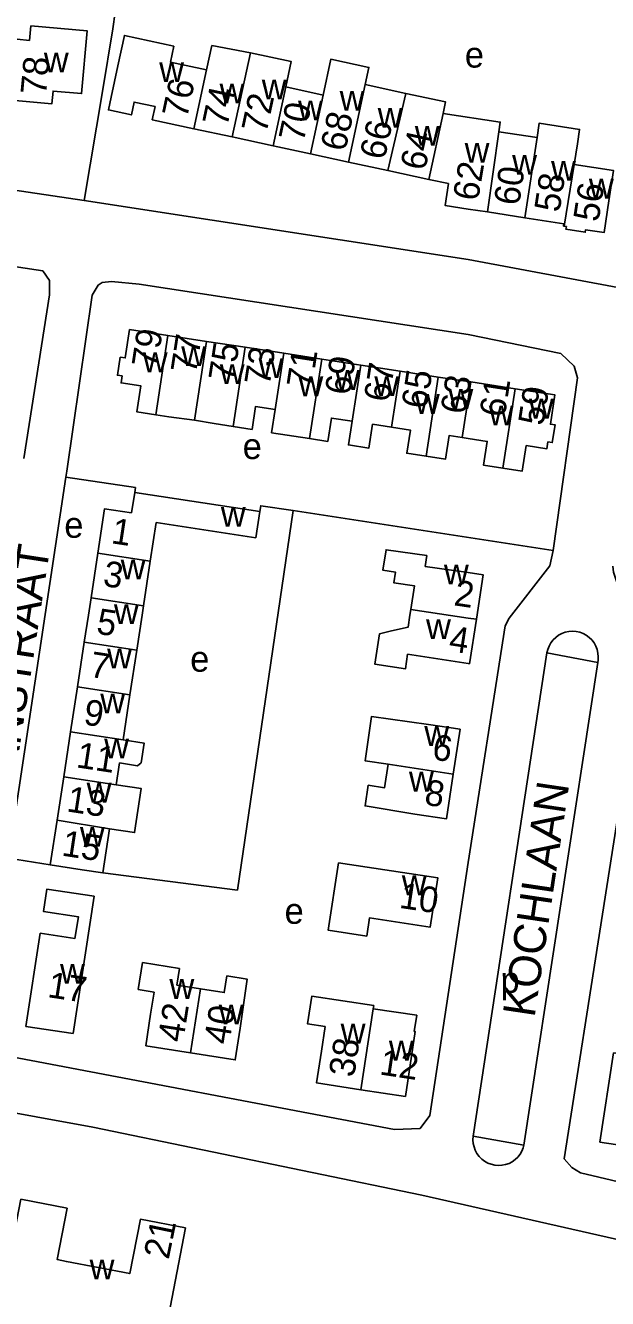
# Model space of a CAD drawing. Extents: x 161093 to 163177, y 379000 to 380904.
# Drawn here: x 161831.1 to 161921.7, y 380393.8 to 380591.7 of the extents above; entities that cross this region are included whole.
import ezdxf

# ---------------------------------------------------------------- set-up
doc = ezdxf.new("R2010")
doc.units = 0
for name, color, linetype in [('BLT_Basislijn', 7, 'Continuous'), ('BLT_Bebouwing', 7, 'Continuous'), ('BLT_Centroide', 7, 'Continuous'), ('BLT_Huisnummer', 7, 'Continuous'), ('BLT_Huisnummer_ tussenligend', 7, 'Continuous'), ('BLT_Onderverdeling_panden', 7, 'Continuous'), ('BLT_Straatnaam', 7, 'Continuous')]:
    doc.layers.add(name, color=color, linetype=linetype)

msp = doc.modelspace()

# ---------------------------------------------------------------- linework, layer by layer
at = {"layer": 'BLT_Basislijn'}
for p, q in [((161765.74, 380575.56), (161840.27, 380564.46)), ((161837.58, 380522.41), (161837.43, 380521.48)), ((161837.43, 380521.48), (161828.52, 380462.26)), ((161872.79, 380516.26), (161864.12, 380457.28)), ((161913.21, 380510.04), (161872.79, 380516.26)), ((161912.24, 380494.13), (161900.78, 380419.03)), ((161912.24, 380494.13), (161920.14, 380492.66)), ((161920.14, 380492.66), (161908.67, 380417.63)), ((161834.99, 380461.19), (161828.52, 380462.26)), ((161843.17, 380459.95), (161864.12, 380457.28)), ((161900.78, 380419.03), (161908.67, 380417.63))]:
    msp.add_line(p, q, dxfattribs=at)
for points in [[(161846.89, 380606.73), (161844.74, 380591.17), (161843.14, 380581.41), (161840.27, 380564.46)], [(161754.75, 380535.6), (161755.89, 380544.7), (161758.65, 380561.45), (161760.72, 380563.99), (161763.58, 380564.09), (161833.83, 380553.53), (161834.89, 380552.05), (161834.86, 380549.82), (161830.91, 380524.37)], [(161924.08, 380550.81), (161900, 380555.29), (161840.27, 380564.46)], [(161913.21, 380510.04), (161917, 380536.92), (161916.46, 380538.73), (161914.39, 380540.68), (161900, 380543.62), (161848.8, 380551.49), (161844.5, 380551.89), (161843.07, 380551.7), (161842.45, 380551.33), (161841.52, 380549.75), (161837.58, 380522.41)], [(161848.13, 380519.09), (161848.24, 380519.84), (161837.43, 380521.48)], [(161872.79, 380516.26), (161867.74, 380517.03), (161867.6, 380516.11)], [(161828.52, 380462.26), (161824.59, 380437.84), (161824.62, 380435.09), (161825.13, 380433.29), (161825.61, 380432.73), (161827.94, 380431.56), (161888.53, 380420.08), (161892.51, 380420.22), (161894.01, 380422.22), (161900, 380461.58), (161905.75, 380498.33), (161906.39, 380499.55), (161912.7, 380507.69), (161913.21, 380510.04)], [(161922.51, 380507.63), (161922.58, 380506.72), (161926.97, 380493.62), (161926.83, 380491.57), (161914.93, 380415.47), (161916.11, 380414.16), (161917.48, 380413.33), (161971.38, 380400.58), (161982.94, 380398.28), (161983.54, 380401.47)], [(161912.24, 380494.13), (161912.37, 380494.69), (161912.57, 380495.21), (161912.85, 380495.71), (161913.2, 380496.16), (161913.6, 380496.55), (161914.06, 380496.89), (161914.56, 380497.16), (161915.09, 380497.35), (161915.65, 380497.47), (161916.21, 380497.51), (161916.78, 380497.47), (161917.33, 380497.35), (161917.86, 380497.15), (161918.36, 380496.88), (161918.82, 380496.54), (161919.22, 380496.15), (161919.56, 380495.69), (161919.84, 380495.2), (161920.05, 380494.67), (161920.17, 380494.12), (161920.22, 380493.55), (161920.19, 380492.99), (161920.14, 380492.66)], [(161790.41, 380429.73), (161841.6, 380420.4), (161892.77, 380409.85), (161973.76, 380391.48), (162004.17, 380383.95)], [(161900.78, 380419.03), (161900.74, 380418.47), (161900.78, 380417.9), (161900.9, 380417.35), (161901.09, 380416.82), (161901.36, 380416.32), (161901.7, 380415.86), (161902.09, 380415.46), (161902.54, 380415.12), (161903.04, 380414.84), (161903.57, 380414.64), (161904.12, 380414.51), (161904.68, 380414.46), (161905.25, 380414.49), (161905.8, 380414.6), (161906.34, 380414.79), (161906.84, 380415.05), (161907.3, 380415.38), (161907.71, 380415.77), (161908.06, 380416.21), (161908.35, 380416.7), (161908.56, 380417.22), (161908.67, 380417.63)]]:
    msp.add_lwpolyline(points, dxfattribs=at)
at = {"layer": 'BLT_Bebouwing'}
for p, q in [((161871.61, 380582.12), (161877.42, 380580.87)), ((161863.31, 380574.35), (161857.35, 380575.63)), ((161869.64, 380572.98), (161863.31, 380574.35)), ((161875.45, 380571.73), (161869.64, 380572.98)), ((161881.38, 380570.45), (161875.45, 380571.73)), ((161887.51, 380569.13), (161881.38, 380570.45)), ((161893.88, 380567.76), (161887.51, 380569.13)), ((161908.8, 380561.8), (161902.97, 380562.69)), ((161859.31, 380542.57), (161853.3, 380543.5)), ((161865.33, 380541.65), (161859.31, 380542.57)), ((161871.31, 380540.73), (161865.33, 380541.65)), ((161877.21, 380539.82), (161871.31, 380540.73)), ((161883.28, 380538.89), (161877.21, 380539.82)), ((161889.4, 380537.95), (161883.28, 380538.89)), ((161895.34, 380537.03), (161889.4, 380537.95)), ((161907.29, 380535.2), (161900.4, 380536.26)), ((161847.65, 380515.92), (161848.13, 380519.09)), ((161848.13, 380519.09), (161867.6, 380516.11)), ((161866.98, 380512.04), (161867.6, 380516.11)), ((161851.48, 380514.41), (161850.56, 380508.4)), ((161851.48, 380514.41), (161866.98, 380512.04)), ((161841.34, 380502.72), (161842.4, 380509.64)), ((161849.5, 380501.48), (161850.56, 380508.4)), ((161840.92, 380500), (161841.34, 380502.72)), ((161840.28, 380495.8), (161840.92, 380500)), ((161849.28, 380500), (161848.45, 380494.55)), ((161849.28, 380500), (161849.5, 380501.48)), ((161900.22, 380492.47), (161901.27, 380499.37)), ((161839.22, 380488.88), (161840.28, 380495.8)), ((161848.45, 380494.55), (161847.39, 380487.63)), ((161838.15, 380481.87), (161839.22, 380488.88)), ((161847.39, 380487.63), (161846.33, 380480.62)), ((161837.09, 380474.9), (161838.15, 380481.87)), ((161836.05, 380468.12), (161837.09, 380474.9)), ((161834.99, 380461.19), (161836.05, 380468.12)), ((161844.22, 380466.82), (161843.17, 380459.95)), ((161841.81, 380456.31), (161838.57, 380434.97)), ((161831.21, 380436.09), (161833.41, 380450.59)), ((161848.68, 380441.81), (161849.34, 380445.99)), ((161849.34, 380445.99), (161855.09, 380445.08)), ((161855.09, 380445.08), (161854.69, 380442.51)), ((161854.69, 380442.51), (161858.38, 380441.93)), ((161851.15, 380441.42), (161848.68, 380441.81)), ((161850.61, 380437.99), (161851.15, 380441.42)), ((161849.84, 380433.05), (161850.61, 380437.99)), ((161838.57, 380434.97), (161831.21, 380436.09)), ((161856.81, 380431.96), (161849.84, 380433.05))]:
    msp.add_line(p, q, dxfattribs=at)
for points in [[(161828.98, 380580.09), (161835.25, 380579.51), (161835.43, 380581.49), (161839.87, 380581.08), (161840.72, 380590.85), (161831.99, 380591.62), (161831.77, 380589.35), (161829.85, 380589.53)], [(161851.31, 380579.07), (161848.04, 380579.78), (161847.61, 380577.78), (161844.04, 380578.55), (161844.46, 380580.55), (161845.52, 380585.43), (161846.53, 380590.13), (161854.21, 380588.47)], [(161854.21, 380588.47), (161853.68, 380585.98), (161859.32, 380584.76)], [(161859.32, 380584.76), (161860.14, 380588.56), (161866.16, 380587.43)], [(161866.16, 380587.43), (161872.46, 380586.08), (161871.61, 380582.12)], [(161877.42, 380580.87), (161878.62, 380586.44), (161884.55, 380585.16), (161883.97, 380582.48)], [(161883.97, 380582.48), (161890.3, 380581.12)], [(161890.3, 380581.12), (161896.47, 380579.79), (161896.09, 380578.01)], [(161857.35, 380575.63), (161850.87, 380577.02), (161851.31, 380579.07)], [(161896.09, 380578.01), (161904.99, 380576.65), (161904.75, 380575.15)], [(161904.75, 380575.15), (161910.7, 380574.24)], [(161910.7, 380574.24), (161911.02, 380576.49), (161917.31, 380575.53), (161916.97, 380573.28), (161916.48, 380570.05)], [(161916.48, 380570.05), (161922.6, 380569.11), (161921.89, 380564.44), (161921.13, 380559.49), (161918.26, 380559.93), (161918.2, 380559.54), (161915.2, 380560), (161915.27, 380560.42), (161914.94, 380560.47)], [(161902.97, 380562.69), (161900, 380563.15), (161896.39, 380563.7), (161896.91, 380567.11), (161893.88, 380567.76)], [(161914.94, 380560.47), (161914.82, 380560.49), (161914.88, 380560.87), (161908.8, 380561.8)], [(161853.3, 380543.5), (161847.34, 380544.41), (161846.66, 380540), (161845.88, 380540.11), (161845.45, 380537.3), (161846.17, 380537.19), (161846, 380536.11), (161849.1, 380535.64), (161848.48, 380531.6), (161851.41, 380531.15)], [(161900.4, 380536.26), (161900, 380536.32), (161895.34, 380537.03)], [(161905.39, 380522.86), (161908.4, 380522.4), (161909.01, 380526.36), (161912.23, 380525.87), (161912.4, 380526.94), (161913.07, 380526.84), (161913.5, 380529.6), (161912.79, 380529.7), (161913.49, 380534.24), (161907.29, 380535.2)], [(161869.97, 380532), (161866.93, 380532.47), (161866.38, 380528.89), (161863.44, 380529.35)], [(161875.31, 380527.46), (161869.41, 380528.36), (161869.97, 380532)], [(161851.41, 380531.15), (161853.42, 380530.84), (161857.42, 380530.31)], [(161863.44, 380529.35), (161860.5, 380529.8), (161857.42, 380530.31)], [(161881.94, 380530.17), (161878.72, 380530.66), (161878.16, 380527.02), (161875.31, 380527.46)], [(161888.07, 380529.23), (161885.12, 380529.68), (161884.56, 380525.99), (161881.37, 380526.48), (161881.94, 380530.17)], [(161893.45, 380524.72), (161890.45, 380525.18), (161891.01, 380528.78), (161888.07, 380529.23)], [(161899.08, 380527.61), (161897.01, 380527.93), (161896.45, 380524.26), (161893.45, 380524.72)], [(161905.39, 380522.86), (161902.39, 380523.32), (161902.96, 380527.02), (161900, 380527.47), (161899.08, 380527.61)], [(161842.4, 380509.64), (161843.45, 380516.56), (161847.65, 380515.92)], [(161901.27, 380499.37), (161902.32, 380506.28), (161900, 380506.63), (161897.38, 380507.03), (161893.31, 380507.59), (161893.55, 380509.27), (161887.23, 380510.18), (161886.74, 380506.99), (161888.67, 380506.71), (161888.42, 380505.06), (161891.62, 380504.58), (161891.08, 380500.89)], [(161900.22, 380492.47), (161900, 380492.5), (161890.58, 380493.93), (161890.23, 380491.66), (161885.49, 380492.38), (161886.21, 380497.12), (161888.07, 380497.57), (161890.67, 380498.17), (161890.94, 380500.01), (161891.08, 380500.89)], [(161887.55, 380476.84), (161883.95, 380477.37), (161884.93, 380484.24), (161893.8, 380483.03), (161898.74, 380482.28), (161897.68, 380475.3)], [(161846.33, 380480.62), (161849.59, 380480.12), (161849.13, 380477.07), (161848.54, 380476.61), (161845.78, 380477.03), (161845.26, 380473.65)], [(161897.68, 380475.3), (161896.63, 380468.35), (161891.68, 380469.1), (161883.95, 380470.35), (161884.44, 380473.56), (161886.99, 380473.18), (161887.55, 380476.84)], [(161845.26, 380473.65), (161849.14, 380473.06), (161848.1, 380466.22), (161844.22, 380466.82)], [(161843.17, 380459.95), (161839.94, 380460.44), (161834.99, 380461.19)], [(161833.41, 380450.59), (161838.84, 380449.77), (161839.39, 380453.12), (161833.96, 380453.94), (161834.49, 380457.42), (161841.81, 380456.31)], [(161858.38, 380441.93), (161862.06, 380441.35), (161862.47, 380443.92), (161865.6, 380443.43), (161864.54, 380435.8), (161863.77, 380430.86), (161856.81, 380431.96)], [(161883.32, 380426.24), (161876.42, 380427.29), (161877.17, 380432.23), (161877.75, 380436.06), (161875.01, 380436.48), (161875.66, 380440.78), (161885.3, 380439.32), (161885.23, 380438.83)], [(161885.23, 380438.83), (161891.98, 380437.81), (161891.6, 380435.29), (161891.75, 380435.27), (161890.23, 380425.2), (161883.32, 380426.24)], [(161922.59, 380431.99), (161929.88, 380430.88), (161927.77, 380416.99), (161920.48, 380418.1), (161922.59, 380431.99)], [(161839.43, 380390.57), (161836.32, 380387.06), (161831.95, 380389.65), (161832.38, 380390.56), (161826.21, 380393.44), (161828.21, 380397.72), (161830.44, 380409.21), (161837.61, 380407.82), (161836.09, 380399.83), (161837.52, 380399.51), (161847.35, 380397.66), (161849.01, 380406.11), (161856.01, 380404.78)], [(161856.01, 380404.78), (161852.11, 380384.29), (161846.46, 380385.36), (161847.16, 380389.03), (161839.43, 380390.57)]]:
    msp.add_lwpolyline(points, dxfattribs=at)
msp.add_lwpolyline([(161879.84, 380461.53), (161895.26, 380459.19), (161894.1, 380451.53), (161884.65, 380452.96), (161884.21, 380450.13), (161878.24, 380451.03)], close=True, dxfattribs=at)
at = {"layer": 'BLT_Onderverdeling_panden'}
for p, q in [((161863.31, 380574.35), (161866.16, 380587.43)), ((161857.35, 380575.63), (161859.32, 380584.76)), ((161869.64, 380572.98), (161871.61, 380582.12)), ((161881.38, 380570.45), (161883.97, 380582.48)), ((161875.45, 380571.73), (161877.42, 380580.87)), ((161893.88, 380567.76), (161896.09, 380578.01)), ((161902.97, 380562.69), (161904.75, 380575.15)), ((161908.8, 380561.8), (161910.7, 380574.24)), ((161914.94, 380560.47), (161916.48, 380570.05)), ((161851.41, 380531.15), (161853.3, 380543.5)), ((161857.42, 380530.31), (161859.31, 380542.57)), ((161863.44, 380529.35), (161865.33, 380541.65)), ((161869.97, 380532), (161871.31, 380540.73)), ((161875.31, 380527.46), (161877.21, 380539.82)), ((161881.94, 380530.17), (161883.28, 380538.89)), ((161888.07, 380529.23), (161889.4, 380537.95)), ((161893.45, 380524.72), (161895.34, 380537.03)), ((161899.08, 380527.61), (161900.4, 380536.26)), ((161905.39, 380522.86), (161907.29, 380535.2)), ((161850.56, 380508.4), (161842.4, 380509.64)), ((161849.5, 380501.48), (161841.34, 380502.72)), ((161891.08, 380500.89), (161900, 380499.56)), ((161901.27, 380499.37), (161900, 380499.56)), ((161848.45, 380494.55), (161840.28, 380495.8)), ((161847.39, 380487.63), (161839.22, 380488.88)), ((161846.33, 380480.62), (161838.15, 380481.87)), ((161887.55, 380476.84), (161897.68, 380475.3)), ((161845.26, 380473.65), (161837.09, 380474.9)), ((161844.22, 380466.82), (161836.05, 380468.12)), ((161858.38, 380441.93), (161856.81, 380431.96)), ((161885.23, 380438.83), (161883.32, 380426.24))]:
    msp.add_line(p, q, dxfattribs=at)
msp.add_lwpolyline([(161887.51, 380569.13), (161890.3, 380581.12)], dxfattribs=at)

# ---------------------------------------------------------------- texts
at = {"layer": 'BLT_Centroide'}
for s, p in [('w', (161834, 380584.39)), ('e', (161899.47, 380585.13)), ('w', (161851.94, 380582.88)), ('w', (161867.89, 380580.2)), ('w', (161861.33, 380579.56)), ('w', (161880, 380578.44)), ('w', (161873.53, 380576.94)), ('w', (161885.92, 380575.77)), ('w', (161891.69, 380573)), ('w', (161899.44, 380570.36)), ('w', (161906.83, 380568.47)), ('w', (161912.88, 380567.55)), ('w', (161918.77, 380564.77)), ('w', (161855.36, 380538.73)), ('w', (161849.38, 380537.78)), ('w', (161867.38, 380536.88)), ('w', (161861.36, 380535.95)), ('w', (161879.3, 380535.03)), ('w', (161873.59, 380534.05)), ('w', (161885.39, 380534.09)), ('w', (161891.7, 380531.3)), ('w', (161896.92, 380532.08)), ('w', (161909.44, 380530.58)), ('w', (161903.19, 380529.52)), ('e', (161864.92, 380524.28)), ('w', (161861.53, 380513.75)), ('e', (161837.18, 380512.04)), ('w', (161845.95, 380505.56)), ('w', (161896.22, 380504.78)), ('w', (161844.9, 380498.62)), ('w', (161893.44, 380496.28)), ('w', (161843.84, 380491.72)), ('e', (161856.76, 380491.22)), ('w', (161842.77, 380484.75)), ('w', (161893.17, 380479.69)), ('w', (161843.38, 380477.75)), ('w', (161890.78, 380472.59)), ('w', (161840.66, 380470.88)), ('w', (161839.61, 380464.03)), ('w', (161889.68, 380456.47)), ('e', (161871.44, 380452.03)), ('w', (161836.52, 380442.7)), ('w', (161853.53, 380440.36)), ('p', (161905.02, 380441.32)), ('w', (161861.2, 380436.38)), ('w', (161880.16, 380433.41)), ('w', (161887.66, 380430.78)), ('w', (161841.12, 380396.75))]:
    msp.add_text(s, height=4, dxfattribs=at).set_placement(p)
at = {"layer": 'BLT_Huisnummer'}
for s, rotation, p in [('78', 84.7429, (161834.34, 380580.76)), ('76', 77.8436, (161856.25, 380577.11)), ('72', 77.8423, (161868.6, 380574.8)), ('68', 77.847, (161880.88, 380571.96)), ('64', 77.8457, (161893.28, 380568.98)), ('62', 80.3525, (161901.51, 380564.27)), ('56', 81.3044, (161920.26, 380561.04)), ('79', 81.264, (161851.59, 380538.32)), ('75', 81.2521, (161863.52, 380536.2)), ('71', 81.2627, (161875.68, 380535.16)), ('67', 81.2617, (161887.68, 380533.02)), ('63', 81.2631, (161899.61, 380531.12)), ('59', 81.2681, (161911.68, 380529.36)), ('1', 351.3255, (161844.35, 380511.21)), ('2', 351.553, (161897.64, 380501.56)), ('5', 351.3276, (161842.04, 380497.15)), ('4', 351.3513, (161896.85, 380494.45)), ('9', 351.3239, (161840.04, 380483.04)), ('6', 351.3529, (161894.25, 380477.61)), ('8', 351.3497, (161893.05, 380470.57)), ('15', 351.3627, (161836.65, 380462.65)), ('10', 351.361, (161889.15, 380454.53)), ('17', 351.3684, (161834.45, 380440.65)), ('42', 81.0613, (161855.65, 380433.48)), ('40', 81.0613, (161862.83, 380433.15)), ('38', 81.39, (161882.24, 380428.06)), ('12', 351.3887, (161886.08, 380428.63)), ('21', 78.4827, (161853.41, 380399.74))]:
    msp.add_text(s, height=4, rotation=rotation, dxfattribs=at).set_placement(p)
at = {"layer": 'BLT_Huisnummer_ tussenligend'}
for s, rotation, p in [('74', 77.8423, (161862.52, 380575.83)), ('70', 77.847, (161874.38, 380573.42)), ('66', 77.8457, (161886.99, 380570.66)), ('60', 81.3044, (161907.9, 380563.56)), ('58', 81.3044, (161914.19, 380562.52)), ('77', 81.2521, (161857.65, 380537.44)), ('73', 81.2627, (161869.11, 380535.55)), ('69', 81.2617, (161881.61, 380534.08)), ('65', 81.2631, (161893.53, 380531.96)), ('61', 81.2681, (161905.67, 380530.65)), ('3', 351.3255, (161843.07, 380504.57)), ('7', 351.3276, (161840.98, 380490.44)), ('11', 351.3239, (161838.91, 380476.37)), ('13', 351.3239, (161837.42, 380469.52))]:
    msp.add_text(s, height=4, rotation=rotation, dxfattribs=at).set_placement(p)
at = {"layer": 'BLT_Straatnaam'}
for s, rotation, p in [('EYKMANSTRAAT', 81.319, (161826.76, 380456.56)), ('KOCHLAAN', 81.5346, (161910.3, 380437.35))]:
    msp.add_text(s, height=5, rotation=rotation, dxfattribs=at).set_placement(p)

doc.saveas('drawing.dxf')
